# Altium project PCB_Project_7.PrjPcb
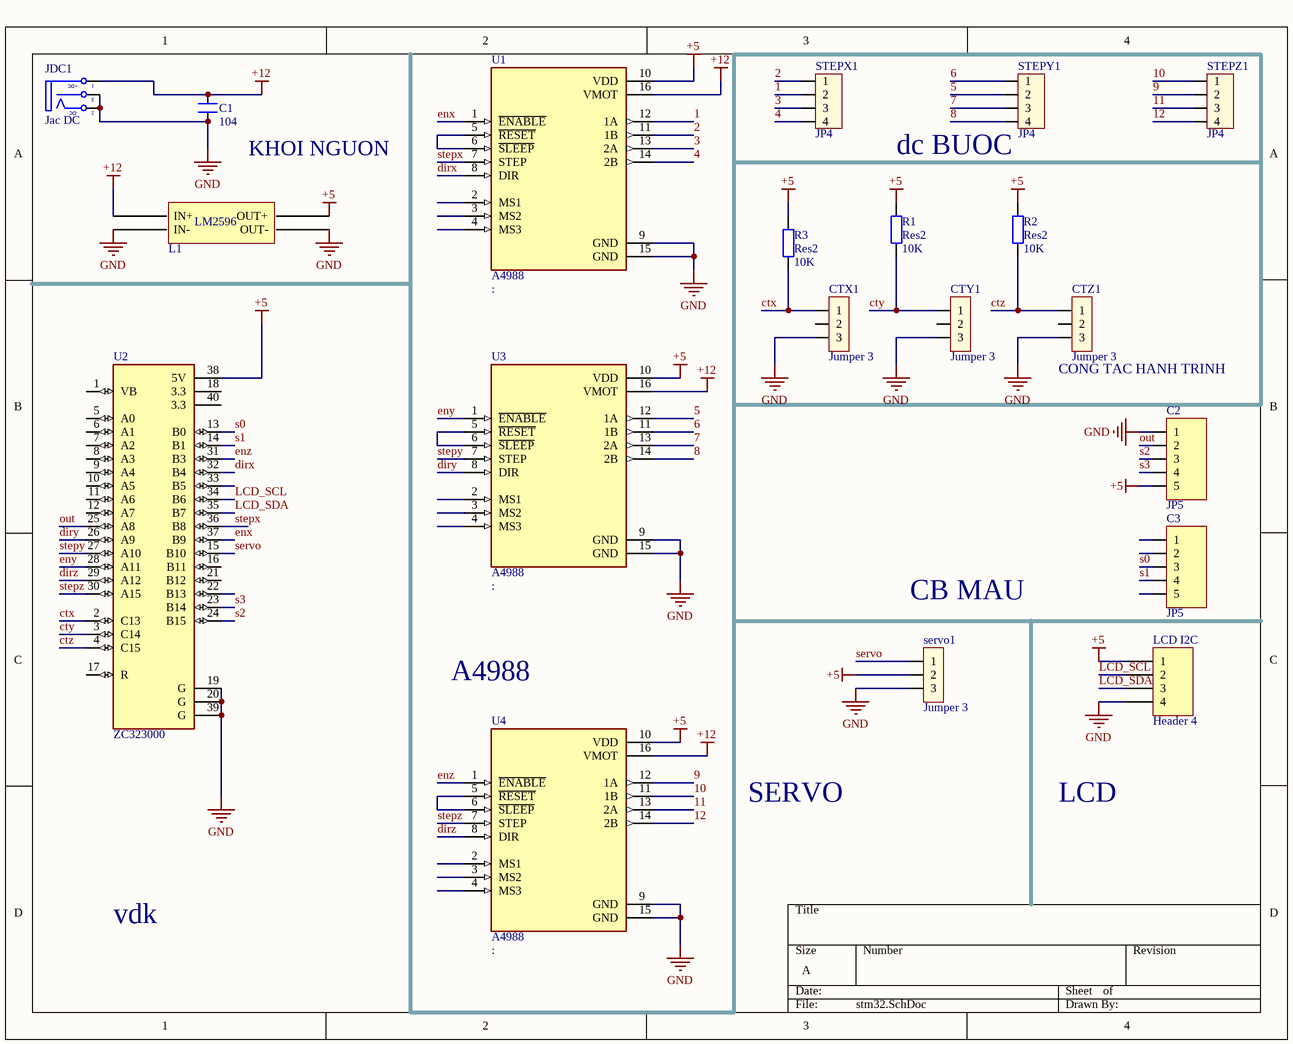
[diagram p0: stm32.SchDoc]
1 sheet, 20 parts. Net scope: global (net labels, ports and power ports of the same name join across sheets).
Board file: stm32.PcbDoc

## Sheet stm32.SchDoc
size A

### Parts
C1  104  [CN3]
C2  JP5  [JP5-C1T]
C3  JP5  [JP5-C1T]
CTX1  Jumper 3  [JP3]
CTY1  Jumper 3  [JP3]
CTZ1  Jumper 3  [JP3]
JDC1  Jac DC  [DC-IN]
L1  BUCK_LM2596  [BUCK_LM2596]  (value not drawn)
LCD_I2C  Header 4  [Header 4]
R1  Res2  value 10K  [AXIAL-0.4]
R2  Res2  value 10K  [AXIAL-0.4]
R3  Res2  value 10K  [AXIAL-0.4]
servo1  Jumper 3  [JP3]
STEPX1  JP4  [CON4]
STEPY1  JP4  [CON4]
STEPZ1  JP4  [CON4]
U1  A4988  [MODULE_A4988_STEPPER_MOTOR_DRIVER_CARRIER_BLACK]
U2  ZC323000  [MODULE_ZC323000]
U3  A4988  [MODULE_A4988_STEPPER_MOTOR_DRIVER_CARRIER_BLACK]
U4  A4988  [MODULE_A4988_STEPPER_MOTOR_DRIVER_CARRIER_BLACK]

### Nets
+5: C2.5 L1.4(OUT+) LCD_I2C.1 R1.2 R2.2 R3.1 servo1.2 U1.10(VDD) U2.38(5V) U3.10(VDD) U4.10(VDD)
+12: C1.2 JDC1.1(T) L1.1(IN+) U1.16(VMOT) U3.16(VMOT) U4.16(VMOT)
GND: C1.1 C2.1 CTX1.3 CTY1.3 CTZ1.3 JDC1.2(TN) JDC1.3(S) L1.2(IN-) L1.3(OUT-) LCD_I2C.4 servo1.3 U1.9(GND) U1.15(GND) U2.19(G) U2.20(G) U2.39(G) U3.9(GND) U3.15(GND) U4.9(GND) U4.15(GND)
1: STEPX1.2 U1.12(1A)
2: STEPX1.1 U1.11(1B)
3: STEPX1.3 U1.13(2A)
4: STEPX1.4 U1.14(2B)
5: STEPY1.2 U3.12(1A)
6: STEPY1.1 U3.11(1B)
7: STEPY1.3 U3.13(2A)
8: STEPY1.4 U3.14(2B)
9: STEPZ1.2 U4.12(1A)
10: STEPZ1.1 U4.11(1B)
11: STEPZ1.3 U4.13(2A)
12: STEPZ1.4 U4.14(2B)
ctx: CTX1.1 R3.2 U2.2(C13)
cty: CTY1.1 R1.1 U2.3(C14)
ctz: CTZ1.1 R2.1 U2.4(C15)
dirx: U1.8(DIR) U2.32(B4)
diry: U2.26(A9) U3.8(DIR)
dirz: U2.29(A12) U4.8(DIR)
enx: U1.1(~{ENABLE}) U2.37(B9)
eny: U2.28(A11) U3.1(~{ENABLE})
enz: U2.31(B3) U4.1(~{ENABLE})
LCD_SCL: LCD_I2C.2 U2.34(B6)
LCD_SDA: LCD_I2C.3 U2.35(B7)
out: C2.2 U2.25(A8)
s0: C3.3 U2.13(B0)
s1: C3.4 U2.14(B1)
s2: C2.3 U2.24(B15)
s3: C2.4 U2.23(B14)
servo: servo1.1 U2.15(B10)
stepx: U1.7(STEP) U2.36(B8)
stepy: U2.27(A10) U3.7(STEP)
stepz: U2.30(A15) U4.7(STEP)
NetU1_5: U1.5(~{RESET}) U1.6(~{SLEEP})
NetU3_5: U3.5(~{RESET}) U3.6(~{SLEEP})
NetU4_5: U4.5(~{RESET}) U4.6(~{SLEEP})

Not connected (* = marked no-connect by the designer): C3 1 2 5; CTX1 2; CTY1 2; CTZ1 2; U1 2(MS1) 3(MS2) 4(MS3); U2 1(VB) 5(A0) 6(A1) 7(A2) 8(A3) 9(A4) 10(A5) 11(A6) 12(A7) 16(B11) 17(R) 18(3.3) 21(B12) 22(B13) 33(B5) 40(3.3); U3 2(MS1) 3(MS2) 4(MS3); U4 2(MS1) 3(MS2) 4(MS3)

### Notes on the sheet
- KHOI NGUON
- (near STEPY1) dc BUOC
- (near CTZ1) CONG TAC HANH TRINH
- CB MAU
- A4988
- SERVO
- LCD
- vdk

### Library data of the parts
C1 = CN3: Cap np W0.3; Value: 0,047uF
C2 C3 = JP5: WR-PHD 2.54 mm Angled Socket Header; Manufacturer: W¨¹rth Elektronik eiSos GmbH; partNo: 613005143121; ComponentLink1 Description: Manufacturer; ComponentLink2 Description: Datasheet; NoPins: 05
CTX1 CTY1 CTZ1 servo1 = JP3: Value: J3
JDC1 = DCIN: Jac DC input
LCD_I2C = Header 4: Header, 4-Pin
R1-R3 = Res2: Resistor
STEPX1 STEPY1 STEPZ1 = Con4: Connector 4
U1 U3 U4 = A4988_STEPPER_MOTOR_DRIVER_CARRIER_BLACK: Stepper motor controler; IC: A4988; 1.2A; Uin mot: 8Ã·35V; MF: Pololu; MP: A4988 STEPPER MOTOR DRIVER CARRIER BLACK
U2 = ZC323000: STM32F103C8T6 ARM STM32 Minimum System Development Board Module For Arduino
